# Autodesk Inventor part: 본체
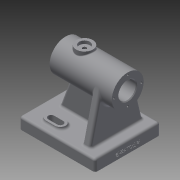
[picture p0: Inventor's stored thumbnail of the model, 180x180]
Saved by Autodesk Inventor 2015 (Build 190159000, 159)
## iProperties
Created: 2022-06
Part Number: 본체
Material: 일반
Document SubType Name: Modeling
Designer: 104589
Density: 1 g/cm^3
Appearance: 기본값
Author: 104589
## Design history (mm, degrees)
sketch "스케치1"
  geometry: L1 (50, -43)-(-50, -43); L2 (-50, -43)-(-50, 43); L3 (-50, 43)-(50, 43); L4 (50, 43)-(50, -43); L5 (50, -43)-(-50, 43); L6 (-50, -43)-(50, 43); 1 further point
  constraints: 12 end point, 2 midpoint, 2 parallel, 1 horizontal, 1 perpendicular
  dimensions: "d0" = 100 distance of L1.start L1.end; "d1" = 86 distance of L1.end L2.end
extrude "돌출1" new body sketch "스케치1" distance "d2" = 15; taper "d3" = 0 deg
sketch "스케치2"
  geometry: L1 (-50, 43)-(-50, -43) reference; L2 (-24, 27)-(-12, 27); L3 (-24, 20)-(-12, 20); L4 (-12, 34)-(-24, 34); A1 r 7 centre (-24, 27) between (-24, 34) and (-24, 20); A2 r 7 centre (-12, 27) between (-12, 20) and (-12, 34); 2 further points
  constraints: 8 end point, 4 point on circle, 4 tangent, 2 centre point, 1 horizontal, 1 midpoint, 1 parallel
  dimensions: "d4" = 26 distance from line of L1 L2.start; "d5" = 12 distance of L2.end L2.start; "d6" = 27 vertical distance of point (0, 0) point (-18, 27); "d7" = 14 distance between parallel lines of L3 L4
extrude "돌출2" join sketch "스케치2" distance "d8" = 3; taper "d9" = 0 deg
sketch "스케치3"
  geometry: L1 (-24, 20)-(-12, 20) reference; L2 (-12, 34)-(-24, 34) reference; L3 (-24, 31)-(-12, 31); L4 (-12, 23)-(-24, 23); A1 r 7 centre (-12, 27) between (-12, 20) and (-12, 34) reference; A2 r 7 centre (-24, 27) between (-24, 34) and (-24, 20) reference; A3 r 4 centre (-12, 27) between (-12, 23) and (-12, 31); A4 r 4 centre (-24, 27) between (-24, 31) and (-24, 23); 1 further point
  constraints: 4 end point, 4 point on circle, 2 centre point, 3 other
  dimensions: "d10" = 8 distance between parallel lines of L3 L4
extrude "돌출3" cut sketch "스케치3" stored distance "d11" = 3; taper "d12" = 0 deg
fillet "모깎기1" dims "d13" = 3
sketch "스케치4"
  geometry: L1 (-50, -43)-(50, -43) reference; L2 (50, -43)-(50, 43) reference; L3 (-50, 43)-(-50, -43) reference; L4 (-35, -5)-(35, -5); L5 (35, -5)-(35, 5); L6 (35, 5)-(-35, 5); L7 (-35, 5)-(-35, -5); L8 (-35, -5)-(35, 5); L9 (35, -5)-(-35, 5); 1 further point
  constraints: 12 end point, 2 midpoint, 2 parallel, 1 horizontal, 1 perpendicular
  dimensions: "d14" = 15 distance between parallel lines of L2 L5; "d15" = 15 distance between parallel lines of L3 L7 (derived); "d16" = 10 distance between parallel lines of L4 L6; "d17" = 43 distance from line of L1 point (0, 0) (derived)
extrude "돌출4" join sketch "스케치4" distance "d18" = 57; taper "d19" = 0 deg
feature "면 기울기1" dims angle "d20" = 20 deg
node "작업 평면1"
sketch "스케치5"
  geometry: L1 (-15, 38)-(-72, 38) reference; L2 (-72, 38)-(-72, 48) reference; L3 (-72, 48)-(-15, 48) reference; L4 (-15, 38)-(-15, 48) reference; L5 (-15, 0)-(-15, 38) reference; L6 (0, 0)-(-15, 0) reference; L7 (0, 86)-(0, 0) reference; L8 (-15, 86)-(0, 86) reference; L9 (-15, 48)-(-15, 86) reference; L10 (-76.814, 22.559)-(-15, 8); L11 (-76.814, 63.441)-(-15, 78); L12 (-76.814, 22.559)-(-76.814, 63.441); L13 (-15, 8)-(-15, 78); L14 (-15, 80)-(-15, 60) reference; A1 r 21 centre (-72, 43) between (-76.814, 22.559) and (-76.814, 63.441); 1 further point
  constraints: 8 end point, 2 point on circle, 2 point on line, 1 centre point, 1 collinear, 1 midpoint, 1 tangent, 1 vertical
  dimensions: "d22" = 42 diameter of A1; "d23" = 8 distance from line of L8 L11.end; "d24" = 8 distance of L10.end L5.start
extrude "돌출5" join sketch "스케치5" distance "d25" = 10; taper "d26" = 0 deg
fillet "모깎기2" dims "d27" = 3
fillet "모깎기3" dims "d28" = 3
fillet "모깎기4" dims "d29" = 3
sketch "스케치6"
  geometry: L1 (-35, 76.814)-(-25, 76.814) reference; L2 (-25, 76.814)-(-25, 72) reference; L3 (-25, 72)-(14.254, 72) reference; L4 (14.254, 72)-(35, 15) reference; L5 (35, 15)-(47, 15) reference; L6 (50, 12)-(50, 0) reference; L7 (50, 0)-(-50, 0) reference; L8 (-50, 0)-(-50, 12) reference; L9 (-47, 15)-(-35, 15) reference; L10 (-35, 15)-(-35, 76.814) reference; L11 (32, 93)-(-50, 93); L12 (-50, 93)-(-50, 72); L13 (-50, 72)-(32, 72); L14 (32, 72)-(32, 93); A1 r 3 centre (47, 12) between (50, 12) and (47, 15) reference; A2 r 3 centre (-47, 12) between (-47, 15) and (-50, 12) reference; 1 further point
  constraints: 8 end point, 2 collinear, 2 parallel, 1 horizontal, 1 perpendicular
  dimensions: "d30" = 72 distance between parallel lines of L7 L3 (derived); "d32" = 82 distance of L11.start L11.end; "d33" = 21 distance of L11.end L12.end
revolve "회전1" sketch "스케치6" stored, may be unused: angle "d34" = 90 deg
fillet "모깎기5" dims "d35" = 3
node "작업 평면2"
sketch "스케치7"
  geometry: L1 (-50, -21)-(-50, 21) reference; L2 (32, -21)-(32, 21) reference; L3 (-38, 18.515)-(-38, -18.515) reference; L4 (-32, 20.441)-(-28, 20.441) reference; L5 (-22, 7)-(-22, 18.515) reference; L6 (19.297, 7)-(-22, 7) reference; L7 (-22, -7)-(19.297, -7) reference; L8 (-22, -18.515)-(-22, -7) reference; L9 (-32, -20.441)-(-28, -20.441) reference; L10 (-50, 21)-(32, 21) reference; L11 (-50, -21)-(32, -21) reference; C1 r 11 at (7, 0); 4 further points; 1 other entity
  constraints: 1 centre point, 1 horizontal alignment, 7 other
  dimensions: "d37" = 22 diameter of C1; "d38" = 25 distance from line of C1.centre L2
extrude "돌출6" join sketch "스케치7" stored distance "d39" = 10; taper "d40" = 0 deg
fillet "모깎기6" dims "d41" = 3
sketch "스케치8"
  geometry: C1 r 11 at (0, 0) reference; C2 r 7 at (0, 0); 1 further point
  constraints: 1 centre point, 1 coincident
  dimensions: "d42" = 14 diameter of C2
extrude "돌출7" cut sketch "스케치8" distance "d43" = 4; taper "d44" = 0 deg
sketch "스케치9"
  geometry: 2 further points
  constraints: 1 horizontal alignment
hole "구멍1" sketch "스케치9" at (0, 0) diameter "d45" = 4.917; stored, may be unused: countersink angle "d49" = 90 deg, drill point angle "d51" = 118 deg; dims "d46" = 12, "d47" = 4, "d48" = 2, "d50" = 21
sketch "스케치10"
  geometry: C1 r 21 at (0, 0) reference; 1 further point
hole "구멍2" sketch "스케치10" at (0, 0) diameter "d52" = 23; stored, may be unused: countersink angle "d56" = 90 deg, drill point angle "d58" = 118 deg; dims "d53" = 12, "d54" = 29, "d55" = 62, "d57" = 21
chamfer "모따기1" distance "d59" = 1; stored, may be unused: second distance "d60" = 2, angle "d61" = 45 deg
fillet "모깎기7" dims "d62" = 1
sketch "스케치11"
  geometry: L1 (0, 0)-(18, 0); C1 r 15.5 at (0, 0) reference; 1 further point
  constraints: 2 end point, 1 horizontal
  dimensions: "d63" = 18 distance of L1.start L1.end
hole "구멍3" sketch "스케치11" at (18, 0) diameter "d64" = 2.459; stored, may be unused: countersink angle "d68" = 90 deg, drill point angle "d70" = 118 deg; dims "d65" = 8, "d66" = 29, "d67" = 62, "d69" = 10
sketch "스케치12"
  geometry: L1 (0, 0)-(-18, 0); C1 r 12.5 at (0, 0) reference; 1 further point
  constraints: 2 end point, 1 horizontal
  dimensions: "d74" = 18 distance of L1.start L1.end
hole "구멍4" sketch "스케치12" at (-18, 0) diameter "d75" = 2.459; stored, may be unused: countersink angle "d79" = 90 deg, drill point angle "d81" = 118 deg; dims "d76" = 8, "d77" = 29, "d78" = 62, "d80" = 10
sketch "스케치13"
  geometry: L1 (0, 80)-(0, 0) reference; 3 further points
  constraints: 1 horizontal alignment, 1 midpoint, 1 other
  dimensions: "d85" = 6 distance from line of L1 point (-6, 40)
feature "엠보싱1" sketch "스케치13" dims "d0" = 100, "d1" = 86, "d86" = 0.5, "d87" = 0
node "솔리드1"
mirror "대칭1"
pattern_circular "원형 패턴1" dims angle "d72" = 360 deg
pattern_circular "원형 패턴2" dims angle "d83" = 360 deg
node "투영된 루프1"
node "절단 모서리 투영1"
node "절단 모서리 투영2"
other parameters: "d21" = -15, "d36" = -96
